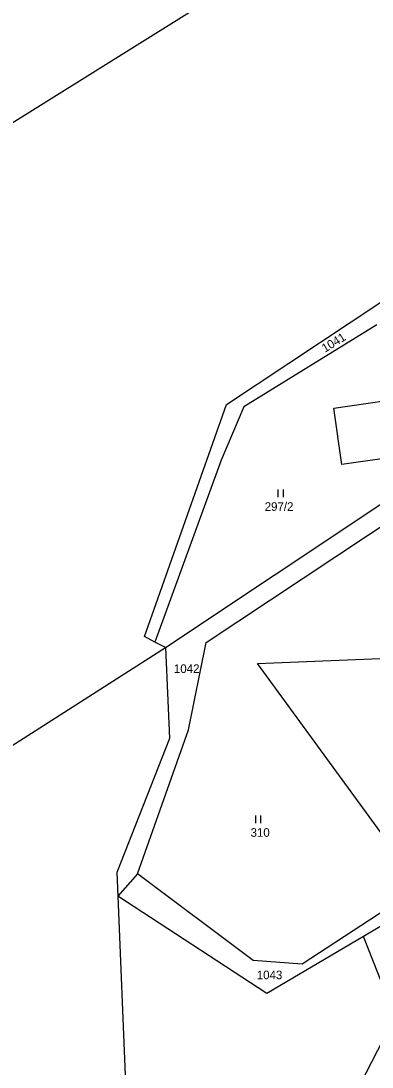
# Model space of a CAD drawing. Extents: x -547623 to -538651, y -1096714 to -1086522.
# Drawn here: x -540163.4 to -540093.9, y -1092227.2 to -1092020.2 of the extents above; entities that cross this region are included whole.
import ezdxf

# ---------------------------------------------------------------- set-up
doc = ezdxf.new("R2010")
doc.units = 0
for name, color, linetype in [('Vrstva 1', 7, 'Continuous'), ('Vrstva 25', 7, 'Continuous'), ('Vrstva 52', 7, 'Continuous'), ('Vrstva 86', 7, 'Continuous')]:
    doc.layers.add(name, color=color, linetype=linetype)

msp = doc.modelspace()

# ---------------------------------------------------------------- linework, layer by layer
at = {"layer": 'Vrstva 1'}
for points in [[(-540342.54, -1092150.94), (-540094.35, -1091996.21)], [(-540122.71, -1092096.1), (-540085.68, -1092071.55)], [(-540092.94, -1092080.3), (-540119.23, -1092096.56)], [(-540101.42, -1092096.78), (-540084.2, -1092094.31)], [(-540138.93, -1092142.01), (-540122.71, -1092096.1)], [(-540119.23, -1092096.56), (-540123.74, -1092107.11)], [(-540099.82, -1092107.97), (-540101.42, -1092096.78)], [(-540123.74, -1092107.11), (-540136.86, -1092143.07)], [(-540082.6, -1092105.5), (-540099.82, -1092107.97)], [(-540126.74, -1092143.19), (-540081.85, -1092113.45)], [(-540134.78, -1092144.13), (-540091.7, -1092115.52)], [(-540136.86, -1092143.07), (-540138.93, -1092142.01)], [(-540186.28, -1092176.97), (-540134.78, -1092144.13)], [(-540134.78, -1092144.13), (-540136.86, -1092143.07)], [(-540134.78, -1092144.13), (-540134, -1092162.17)], [(-540130.22, -1092160.46), (-540126.74, -1092143.19)], [(-540116.55, -1092147.31), (-540072.84, -1092145.56)], [(-540084.25, -1092191.47), (-540116.55, -1092147.31)], [(-540140.32, -1092188.93), (-540130.22, -1092160.46)], [(-540134, -1092162.17), (-540144.37, -1092188.69)], [(-540144.37, -1092188.69), (-540144.18, -1092193.37)], [(-540140.32, -1092188.93), (-540144.18, -1092193.37)], [(-540117.41, -1092206.08), (-540140.32, -1092188.93)], [(-540084.25, -1092191.47), (-540107.69, -1092206.8)], [(-540077.15, -1092190.45), (-540095.57, -1092201.32)], [(-540114.73, -1092212.62), (-540144.18, -1092193.37)], [(-540144.18, -1092193.37), (-540142.66, -1092230.4)], [(-540095.57, -1092201.32), (-540114.73, -1092212.62)], [(-540081.83, -1092236.09), (-540095.57, -1092201.32)], [(-540107.69, -1092206.8), (-540117.41, -1092206.08)]]:
    msp.add_lwpolyline(points, dxfattribs=at)
at = {"layer": 'Vrstva 25'}
for p, q in [((-540112.43, -1092114.42), (-540112.43, -1092112.92)), ((-540111.43, -1092114.42), (-540111.43, -1092112.92)), ((-540116.86, -1092178.9), (-540116.86, -1092177.4)), ((-540115.86, -1092178.9), (-540115.86, -1092177.4))]:
    msp.add_line(p, q, dxfattribs=at)
at = {"layer": 'Vrstva 52'}
msp.add_lwpolyline([(-540135.65, -1092307.84), (-540133.5, -1092303), (-540113.38, -1092263.93), (-540089.3, -1092217.18), (-540084.86, -1092208.57), (-540078.62, -1092196.44), (-540075.24, -1092189.88), (-540074.82, -1092189.07), (-540062.93, -1092165.99), (-540061.15, -1092162.52), (-540058.58, -1092157.54), (-540056.5, -1092153.5), (-540052.11, -1092142.12), (-540050.37, -1092137.62), (-540048.51, -1092132.79), (-540048.41, -1092132.53), (-540047.81, -1092130.98), (-540043, -1092118.5), (-540041.85, -1092114.42), (-540040.33, -1092109.07), (-540035.11, -1092090.57), (-540032.13, -1092080.03), (-540031.62, -1092078.22), (-540030, -1092072.5)], dxfattribs=at)

# ---------------------------------------------------------------- texts
at = {"layer": 'Vrstva 86'}
msp.add_text('1041', height=1.7, rotation=31.5174, dxfattribs=at).set_placement((-540103.19, -1092085.86))
for s, p in [('297/2', (-540115.12, -1092117.12)), ('1042', (-540133.1, -1092149.19)), ('310', (-540117.92, -1092181.6)), ('1043', (-540116.69, -1092209.78))]:
    msp.add_text(s, height=1.7, dxfattribs=at).set_placement(p)

doc.saveas('drawing.dxf')
